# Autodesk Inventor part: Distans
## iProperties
Shininess: 64.0
Length Units: 11269
Angle Units: 11279
Time Units: 11290
Mass Units: 11283
Length Display Precision: 3
Angle Display Precision: 2
Created: 2001-12
Part Number: Distans
Material: Silicon Nitride
Document SubType Name: Modeling
Designer: Tobben
Density: 1 g/cm^3
Density: 0.0
Volumn: 0.0
Area: 0.0
PropertySet Name: Model Information
Control State: 0
Master: False
Checked Out: False
Author: Tobben
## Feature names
1. Extrusion1
2. Fillet1
3. Fillet2
